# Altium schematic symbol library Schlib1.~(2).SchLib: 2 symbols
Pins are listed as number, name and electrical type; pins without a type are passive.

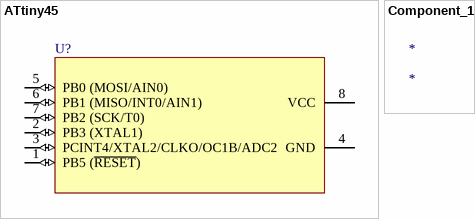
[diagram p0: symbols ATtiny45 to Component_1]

## ATtiny45
designator U?
8-Bit AVR Microcontroller with 1K Byte of Flash Memory
3D model 8S2 (8-Pin Small Outline Package 1.27 mm Pitch)
footprint SOIC8
footprint 8S2_N (SOP, 8-Leads, Body 5.3x5.3mm, Pitch 1.27mm, IPC Medium Density)
footprint 8S2_M (SOP, 8-Leads, Body 5.3x5.3mm, Pitch 1.27mm, IPC Low Density)
pins: 1 PB5 (~{RESET}) (io), 2 PB3 (XTAL1) (io), 3 PCINT4/XTAL2/CLKO/OC1B/ADC2 (io), 4 GND (power), 5 PB0 (MOSI/AIN0) (io), 6 PB1 (MISO/INT0/AIN1) (io), 7 PB2 (SCK/T0) (io), 8 VCC (power)

## Component_1
designator *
